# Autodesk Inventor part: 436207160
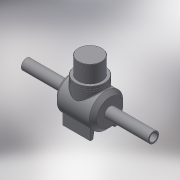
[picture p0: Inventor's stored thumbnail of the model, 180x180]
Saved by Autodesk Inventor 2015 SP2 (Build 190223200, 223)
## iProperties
Created: 2017-08
Part Number: 436207160
Material: Generic
Description: PLASSON PE BALL VALVE 160
Document SubType Name: Modeling
Designer: Кирилл
Density: 1 g/cm^3
Appearance: Default
Author: Кирилл
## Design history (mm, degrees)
derived "436207.ipt"
feature "Solid1::436207.ipt"
feature "Solid2::436207.ipt"
tag "TaggingFeature1"
body "Solid1"
other parameters: "d3" = 182, "d5" = 88, "d6" = 16.5, "d10" = 85, "d11" = 68, "d12" = 0.85, "d13" = 4, "d14" = 4, "d16" = 100 deg, "d18" = 16, "d20" = 93, "d21" = 0, "d22" = 0.85, "d26" = 16, "d28" = 0, "d29" = 1.7, "s_" = 16, "L_1" = 182, "B_" = 93, "E_1" = 85
